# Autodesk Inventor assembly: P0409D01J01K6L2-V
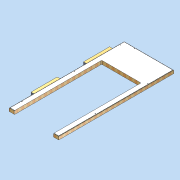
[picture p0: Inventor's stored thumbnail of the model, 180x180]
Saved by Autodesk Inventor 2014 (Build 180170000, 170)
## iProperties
Created: 2011-04
Part Number: P0409D01J01K6L2-V
Document SubType Name: Assembly
Designer: david.appleford
Description: 1w x 2.25w 01 Panel - 6 Locks 2 Lugs
Mass: 20000 g
Surface Area: 37268.7 cm^2
Volume: 102414 cm^3
Density: 0.195287 g/cm^3
Cost Center: £155.00
Justset: False
Title: 1w x 2.25w 01 Panel - 6 Locks 2 Lugs
Author: david.appleford
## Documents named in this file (3)
- C:\Documents and Settings\john.everitt\Local Settings\My Documents\Vault\Production MkII\Virtual Elements\Virtual Walls\Virtual Timber + MgO\P0409D01J01K6L2-V.iam
- C:\Documents and Settings\john.everitt\Local Settings\My Documents\Vault\Production MkII\VIRTUAL ELEMENTS\Virtual Lugs\Superceded Lugs\LA02M3V.ipt
- C:\Documents and Settings\john.everitt\Local Settings\My Documents\Vault\Production MkII\Virtual Elements\Virtual Walls\Virtual Timber + MgO\P0409D01J01K7-V.ipt
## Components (3 placed, 2 different names)
1. P0409D01J01K7-V:1 — Mate:5, Mate:6, Flush:9, Flush:10
2. LA02M3V:5 — Mate:6, Flush:9, Mate:12
3. LA02M3V:2 — Mate:5, Flush:10, Mate:12
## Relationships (5: Mate 3, Flush 2)
- Mate:5: P0409D01J01K7-V:1 ↔ LA02M3V:2
- Mate:6: P0409D01J01K7-V:1 ↔ LA02M3V:5
- Flush:9: P0409D01J01K7-V:1 ↔ LA02M3V:5
- Flush:10: P0409D01J01K7-V:1 ↔ LA02M3V:2
- Mate:12: LA02M3V:5 ↔ LA02M3V:2
## Named parameters: t = 1 mm, Cl = 2 mm
